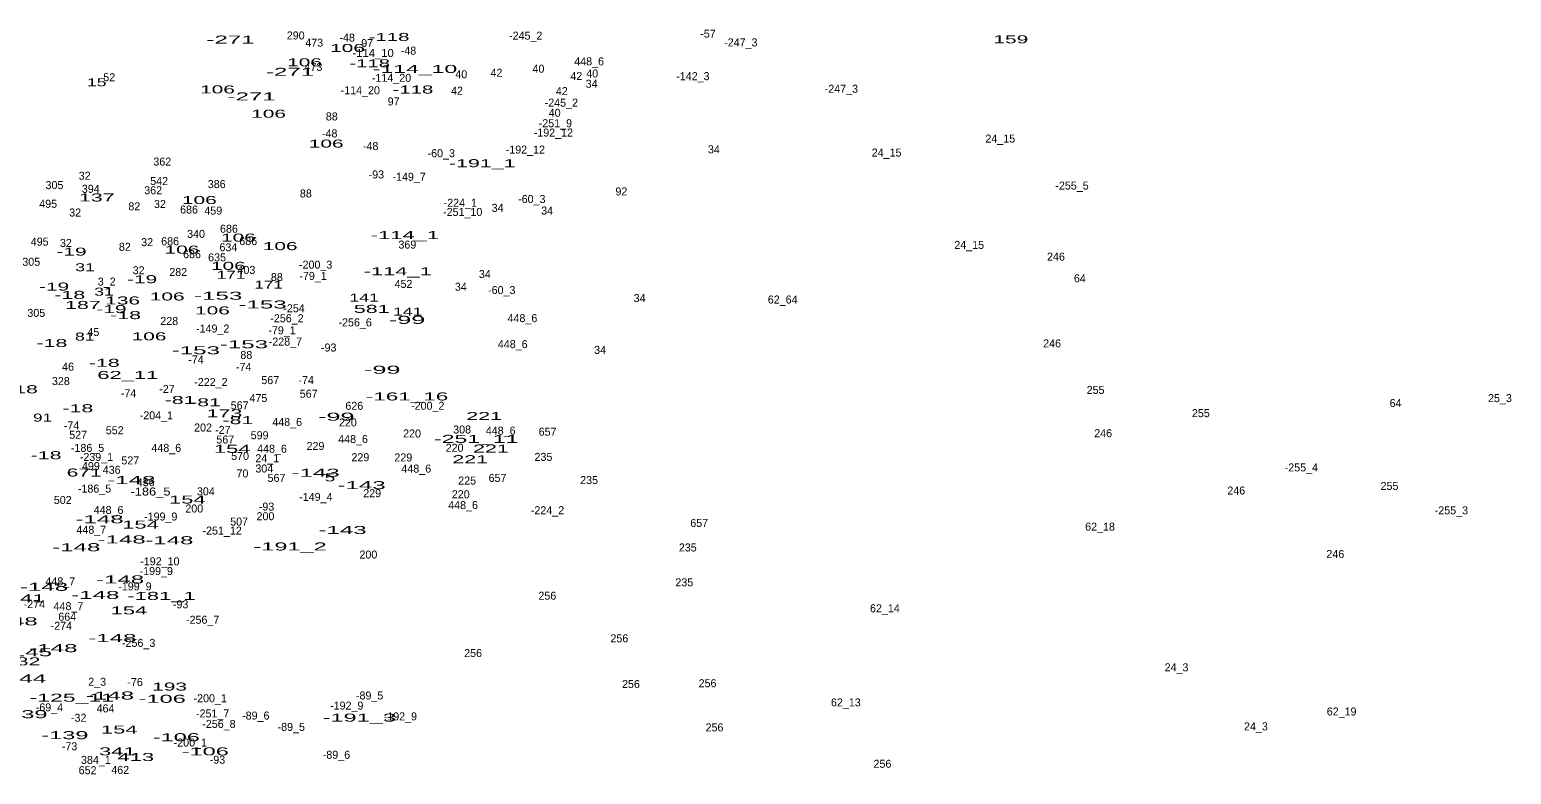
# Model space of a CAD drawing. Extents: x -661742 to -657295, y -1002932 to -996888.
# Drawn here: x -660015 to -659274, y -1000678 to -1000306 of the extents above; entities that cross this region are included whole.
import ezdxf
from ezdxf.enums import TextEntityAlignment as Align

# ---------------------------------------------------------------- set-up
doc = ezdxf.new("R2010")
doc.units = 0
doc.header["$LTSCALE"] = 1.6
doc.layers.add('24', color=7, linetype='Continuous')

msp = doc.modelspace()

# ---------------------------------------------------------------- texts
at = {"layer": '24'}
for s, width, p in [('-271', 2.25, (-659914.595, -1000313.42)), ('-118', 1.9, (-659835.317, -1000312.09)), ('159', 1.95, (-659524.523, -1000313.28)), ('106', 1.95, (-659856.109, -1000317.6)), ('-114_10', 1.05, (-659843.3, -1000320.12)), ('106', 1.95, (-659877.579, -1000324.76)), ('-118', 1.9, (-659845.007, -1000325.26)), ('-114_10', 2.15, (-659822.376, -1000328.08)), ('15', 1.65, (-659981.467, -1000334.75)), ('-271', 2.25, (-659884.835, -1000329.52)), ('106', 1.95, (-659921.089, -1000338.3)), ('-271', 2.25, (-659904.035, -1000341.83)), ('-118', 1.9, (-659823.397, -1000338.35)), ('106', 1.95, (-659895.559, -1000350.45)), ('106', 1.95, (-659866.749, -1000365.37)), ('-191_1', 2, (-659788.749, -1000375.16)), ('137', 2, (-659981.433, -1000392.29)), ('106', 1.95, (-659930.179, -1000393.57)), ('106', 1.95, (-659910.649, -1000412.34)), ('106', 1.95, (-659889.759, -1000416.6)), ('-114_1', 2.05, (-659827.419, -1000411.07)), ('-19', 1.95, (-659994.065, -1000419.35)), ('106', 1.95, (-659938.879, -1000418.34)), ('31', 1.65, (-659987.287, -1000427.15)), ('106', 1.95, (-659915.679, -1000426.46)), ('171', 1.6, (-659914.289, -1000430.9)), ('-114_1', 2.05, (-659831.009, -1000429.15)), ('-19', 1.95, (-660002.785, -1000436.8)), ('31', 1.65, (-659977.817, -1000439.34)), ('-19', 1.95, (-659958.775, -1000433.11)), ('171', 1.6, (-659895.529, -1000435.84)), ('-18', 2, (-659994.951, -1000440.96)), ('187', 2, (-659988.363, -1000445.98)), ('136', 1.95, (-659968.503, -1000443.75)), ('106', 1.95, (-659946.229, -1000441.75)), ('-153', 2.25, (-659920.761, -1000441.38)), ('-153', 2.25, (-659898.561, -1000445.75)), ('141', 1.65, (-659847.779, -1000442.31)), ('-19', 1.95, (-659974.095, -1000448.05)), ('-18', 2, (-659967.031, -1000451.05)), ('106', 1.95, (-659923.599, -1000448.71)), ('581', 2, (-659844.007, -1000447.94)), ('-99', 2.35, (-659826.343, -1000453.43)), ('141', 1.65, (-659825.969, -1000449.28)), ('-18', 2, (-660003.871, -1000465.01)), ('81', 1.65, (-659987.427, -1000461.77)), ('106', 1.95, (-659955.319, -1000461.67)), ('-153', 2.25, (-659931.901, -1000468.63)), ('-153', 2.25, (-659907.861, -1000465.63)), ('-18', 2, (-659977.701, -1000474.9)), ('62_11', 2.05, (-659965.91, -1000480.96)), ('-99', 2.35, (-659838.753, -1000478.35)), ('-18', 2, (-660018.601, -1000488.09)), ('-18', 2, (-659990.881, -1000497.59)), ('-81', 2, (-659939.771, -1000493.45)), ('-81', 2, (-659927.071, -1000494.62)), ('-161_16', 2.1, (-659826.333, -1000491.69)), ('91', 1.6, (-660008.553, -1000502.26)), ('173', 2, (-659917.633, -1000500.12)), ('-81', 2, (-659910.891, -1000503.54)), ('-99', 2.35, (-659861.723, -1000501.82)), ('221', 2, (-659787.797, -1000501.48)), ('-251_11', 2.15, (-659791.744, -1000512.88)), ('154', 2.05, (-659913.743, -1000517.86)), ('221', 2, (-659784.407, -1000517.73)), ('-18', 2, (-660006.781, -1000521.06)), ('221', 2, (-659794.757, -1000523.05)), ('671', 1.95, (-659987.757, -1000529.71)), ('-148', 2.25, (-659964.166, -1000533.47)), ('-143', 2.25, (-659872.056, -1000529.81)), ('5', 1.8, (-659864.871, -1000532.13)), ('-186_5', 1.2, (-659954.591, -1000539.19)), ('-143', 2.25, (-659849.076, -1000536.02)), ('154', 2.05, (-659936.183, -1000543.2)), ('-148', 2.25, (-659980.056, -1000553.06)), ('154', 2.05, (-659959.573, -1000555.72)), ('-148', 2.25, (-659969.006, -1000563.14)), ('-148', 2.25, (-659945.166, -1000563.53)), ('-143', 2.25, (-659858.576, -1000558.42)), ('-148', 2.25, (-659991.686, -1000567.02)), ('-191_2', 2.2, (-659884.823, -1000566.65)), ('-148', 2.25, (-660007.786, -1000586.8)), ('-148', 2.25, (-659969.786, -1000583.12)), ('-41', 2.05, (-660015.446, -1000592.55)), ('-148', 2.25, (-659982.186, -1000590.88)), ('-181_1', 2.05, (-659949.084, -1000591.34)), ('154', 2.05, (-659965.373, -1000598.57)), ('-148', 2.25, (-660022.996, -1000604.06)), ('-148', 2.25, (-659973.656, -1000612.4)), ('-145', 2.25, (-660015.826, -1000619.48)), ('132', 2, (-660018.537, -1000624.04)), ('-148', 2.25, (-660003.126, -1000617.45)), ('-144', 2.3, (-660018.932, -1000632.61)), ('193', 1.95, (-659945.043, -1000636.64)), ('-125_11', 2.15, (-659993.914, -1000642.19)), ('-148', 2.25, (-659974.826, -1000641.11)), ('-106', 2.2, (-659948.721, -1000642.74)), ('-139', 2.2, (-660017.855, -1000650.43)), ('-191_3', 2.2, (-659850.243, -1000652.15)), ('-139', 2.2, (-659997.405, -1000660.91)), ('154', 2.05, (-659970.193, -1000658.1)), ('-106', 2.2, (-659941.651, -1000661.94)), ('341', 2.05, (-659971.173, -1000669.02)), ('413', 2.05, (-659961.913, -1000671.83)), ('-106', 2.2, (-659927.201, -1000669.02))]:
    msp.add_text(s, height=4, dxfattribs=dict(at, width=width)).set_placement(p, align=Align.CENTER)
for s, p in [('290', (-659881.997, -1000311.34)), ('-48', (-659856.269, -1000312.41)), ('-245_2', (-659767.027, -1000311.45)), ('-57', (-659675.931, -1000310.45)), ('473', (-659872.757, -1000314.96)), ('97', (-659846.288, -1000315.2)), ('-48', (-659825.639, -1000318.91)), ('-247_3', (-659659.502, -1000314.82)), ('473', (-659873.137, -1000327.08)), ('40', (-659760.665, -1000327.94)), ('448_6', (-659735.329, -1000324.3)), ('52', (-659975.187, -1000332.2)), ('-114_20', (-659834.097, -1000332.52)), ('40', (-659799.245, -1000330.75)), ('42', (-659781.661, -1000329.97)), ('42', (-659741.731, -1000331.62)), ('34', (-659734.091, -1000335.47)), ('40', (-659733.785, -1000330.36)), ('-142_3', (-659683.47, -1000331.69)), ('-114_20', (-659849.707, -1000338.74)), ('42', (-659801.391, -1000338.97)), ('42', (-659748.981, -1000339.15)), ('-247_3', (-659609.242, -1000337.99)), ('97', (-659833.038, -1000344.32)), ('-245_2', (-659749.227, -1000344.92)), ('40', (-659752.545, -1000349.98)), ('88', (-659863.957, -1000351.82)), ('-251_9', (-659752.212, -1000355.2)), ('-48', (-659864.999, -1000360.29)), ('-192_12', (-659753.195, -1000359.85)), ('24_15', (-659529.793, -1000362.87)), ('-48', (-659844.539, -1000366.6)), ('-60_3', (-659809.242, -1000370.19)), ('-192_12', (-659767.215, -1000368.37)), ('34', (-659672.981, -1000368.26)), ('24_15', (-659586.643, -1000369.85)), ('362', (-659948.693, -1000374.36)), ('305', (-660002.591, -1000386.11)), ('32', (-659987.487, -1000381.43)), ('542', (-659950.281, -1000384.09)), ('386', (-659921.483, -1000385.61)), ('-93', (-659841.69, -1000380.79)), ('-149_7', (-659825.302, -1000381.95)), ('-255_5', (-659493.952, -1000386.35)), ('394', (-659984.447, -1000387.98)), ('362', (-659953.243, -1000388.68)), ('88', (-659876.917, -1000390.28)), ('-60_3', (-659763.982, -1000393.07)), ('92', (-659719.203, -1000389.26)), ('495', (-660005.747, -1000395.44)), ('32', (-659992.227, -1000399.81)), ('82', (-659962.677, -1000396.72)), ('32', (-659949.877, -1000395.55)), ('686', (-659935.328, -1000398.32)), ('459', (-659923.207, -1000398.85)), ('-251_10', (-659798.523, -1000399.52)), ('-224_1', (-659799.7, -1000394.92)), ('34', (-659781.091, -1000397.47)), ('34', (-659756.331, -1000398.83)), ('686', (-659915.368, -1000407.92)), ('495', (-660009.967, -1000414.35)), ('32', (-659996.867, -1000415)), ('82', (-659967.417, -1000416.94)), ('32', (-659956.257, -1000414.61)), ('686', (-659944.788, -1000414.17)), ('340', (-659931.815, -1000410.49)), ('686', (-659905.728, -1000414.09)), ('369', (-659826.198, -1000415.83)), ('24_15', (-659545.343, -1000415.99)), ('305', (-660014.181, -1000424.41)), ('686', (-659933.828, -1000420.62)), ('635', (-659921.313, -1000422.21)), ('634', (-659915.647, -1000417.17)), ('246', (-659501.977, -1000421.85)), ('32', (-659960.507, -1000428.64)), ('282', (-659940.737, -1000429.53)), ('403', (-659906.645, -1000428.49)), ('-200_3', (-659872.03, -1000425.85)), ('-79_1', (-659873.317, -1000431.49)), ('34', (-659787.471, -1000430.56)), ('3_2', (-659976.476, -1000434.31)), ('88', (-659891.427, -1000432.05)), ('452', (-659828.121, -1000435.47)), ('34', (-659799.461, -1000436.9)), ('-60_3', (-659779.002, -1000438.55)), ('64', (-659490.027, -1000432.69)), ('34', (-659710.111, -1000442.55)), ('62_64', (-659638.59, -1000443.28)), ('305', (-660011.671, -1000449.95)), ('228', (-659945.227, -1000453.99)), ('-256_2', (-659886.358, -1000452.63)), ('-254', (-659882.839, -1000447.64)), ('448_6', (-659768.669, -1000452.57)), ('45', (-659983.131, -1000459.51)), ('-149_2', (-659923.486, -1000457.76)), ('-79_1', (-659888.827, -1000458.64)), ('-256_6', (-659852.283, -1000454.69)), ('-228_7', (-659887.158, -1000464.3)), ('-93', (-659865.5, -1000467.26)), ('448_6', (-659773.519, -1000465.57)), ('34', (-659729.841, -1000468.44)), ('246', (-659503.907, -1000465.19)), ('-74', (-659931.845, -1000473.24)), ('88', (-659906.697, -1000470.94)), ('46', (-659995.797, -1000476.83)), ('-74', (-659907.995, -1000476.92)), ('567', (-659894.708, -1000483.54)), ('-74', (-659876.785, -1000483.52)), ('328', (-659999.397, -1000484.01)), ('-74', (-659965.575, -1000490.11)), ('-27', (-659946.351, -1000487.95)), ('-222_2', (-659924.392, -1000484.49)), ('567', (-659875.518, -1000490.33)), ('255', (-659482.157, -1000488.43)), ('567', (-659910.028, -1000496.15)), ('475', (-659900.637, -1000492.51)), ('626', (-659852.718, -1000496.38)), ('-200_2', (-659815.98, -1000496.35)), ('64', (-659332.217, -1000494.99)), ('25_3', (-659280.045, -1000492.53)), ('-204_1', (-659951.654, -1000501.15)), ('448_6', (-659886.269, -1000504.47)), ('220', (-659855.941, -1000504.68)), ('255', (-659429.557, -1000500.04)), ('-74', (-659994.075, -1000506.21)), ('527', (-659990.753, -1000510.85)), ('552', (-659972.477, -1000508.58)), ('202', (-659928.321, -1000507.22)), ('-27', (-659918.431, -1000508.41)), ('567', (-659917.198, -1000513.21)), ('599', (-659900.028, -1000511.08)), ('448_6', (-659853.319, -1000513)), ('220', (-659823.841, -1000510.19)), ('308', (-659798.821, -1000508.21)), ('448_6', (-659779.529, -1000508.76)), ('657', (-659756.108, -1000509.31)), ('246', (-659478.377, -1000510.07)), ('-186_5', (-659986.042, -1000517.38)), ('448_6', (-659946.689, -1000517.4)), ('448_6', (-659893.839, -1000517.83)), ('229', (-659872.113, -1000516.45)), ('220', (-659802.571, -1000517.34)), ('-239_1', (-659981.592, -1000521.94)), ('499', (-659984.393, -1000526.49)), ('527', (-659964.683, -1000523.65)), ('570', (-659909.807, -1000521.44)), ('304', (-659897.705, -1000527.69)), ('24_1', (-659896.223, -1000522.56)), ('229', (-659849.673, -1000522.06)), ('229', (-659828.213, -1000522.16)), ('448_6', (-659821.719, -1000527.74)), ('235', (-659758.157, -1000521.88)), ('-255_4', (-659379.307, -1000527.15)), ('436', (-659973.987, -1000528.34)), ('436', (-659956.977, -1000534.53)), ('70', (-659908.627, -1000530.16)), ('567', (-659891.608, -1000532.41)), ('225', (-659796.307, -1000533.72)), ('657', (-659781.118, -1000532.39)), ('235', (-659735.337, -1000533.48)), ('-186_5', (-659982.562, -1000537.74)), ('304', (-659926.905, -1000539.11)), ('-149_4', (-659871.93, -1000541.88)), ('229', (-659843.783, -1000540.05)), ('220', (-659799.481, -1000540.56)), ('246', (-659411.847, -1000538.7)), ('255', (-659335.257, -1000536.42)), ('502', (-659998.451, -1000543.41)), ('448_6', (-659975.529, -1000548.4)), ('200', (-659932.695, -1000547.68)), ('-93', (-659896.59, -1000546.73)), ('448_6', (-659798.339, -1000545.97)), ('-224_2', (-659756.127, -1000548.54)), ('-255_3', (-659304.312, -1000548.6)), ('-199_9', (-659949.472, -1000551.68)), ('507', (-659910.297, -1000554.22)), ('200', (-659897.105, -1000551.54)), ('657', (-659680.298, -1000554.89)), ('62_18', (-659479.944, -1000556.75)), ('448_7', (-659984.169, -1000558.29)), ('-251_12', (-659918.759, -1000558.71)), ('200', (-659845.665, -1000570.7)), ('235', (-659686.017, -1000567.15)), ('246', (-659362.337, -1000570.43)), ('-199_9', (-659951.702, -1000578.93)), ('-192_10', (-659949.899, -1000574.08)), ('448_7', (-659999.679, -1000584.08)), ('-199_9', (-659962.362, -1000586.59)), ('235', (-659687.757, -1000584.56)), ('256', (-659756.203, -1000591.26)), ('-274', (-660012.615, -1000595.45)), ('448_7', (-659995.609, -1000596.49)), ('664', (-659996.213, -1000601.73)), ('-93', (-659939.52, -1000595.54)), ('62_14', (-659587.488, -1000597.53)), ('-274', (-659999.145, -1000606.28)), ('-256_7', (-659928.514, -1000603.26)), ('-256_3', (-659960.508, -1000614.83)), ('256', (-659720.223, -1000612.54)), ('256', (-659793.333, -1000619.89)), ('24_3', (-659441.71, -1000627.02)), ('2_3', (-659981.246, -1000634.24)), ('-76', (-659962.285, -1000634.39)), ('256', (-659714.423, -1000635.37)), ('256', (-659676.133, -1000634.98)), ('-200_1', (-659924.744, -1000642.49)), ('-192_9', (-659856.477, -1000646.15)), ('-89_5', (-659845.048, -1000641.08)), ('62_13', (-659607.004, -1000644.55)), ('-69_4', (-660005.098, -1000647.01)), ('-32', (-659990.475, -1000652.22)), ('464', (-659977.061, -1000647.54)), ('-251_7', (-659923.522, -1000650.08)), ('-89_6', (-659901.953, -1000651.13)), ('-192_9', (-659829.687, -1000651.54)), ('62_19', (-659359.17, -1000649.09)), ('-256_8', (-659920.378, -1000655.31)), ('-89_5', (-659884.218, -1000656.78)), ('256', (-659672.653, -1000657.04)), ('24_3', (-659402.02, -1000656.53)), ('-73', (-659995.041, -1000666.47)), ('-200_1', (-659934.674, -1000664.61)), ('384_1', (-659981.883, -1000673.29)), ('-93', (-659921.11, -1000673.16)), ('-89_6', (-659861.633, -1000670.71)), ('256', (-659588.713, -1000675.22)), ('652', (-659986.043, -1000678.44)), ('462', (-659969.727, -1000678.29))]:
    msp.add_text(s, height=4, dxfattribs=at).set_placement(p, align=Align.CENTER)

doc.saveas('drawing.dxf')
